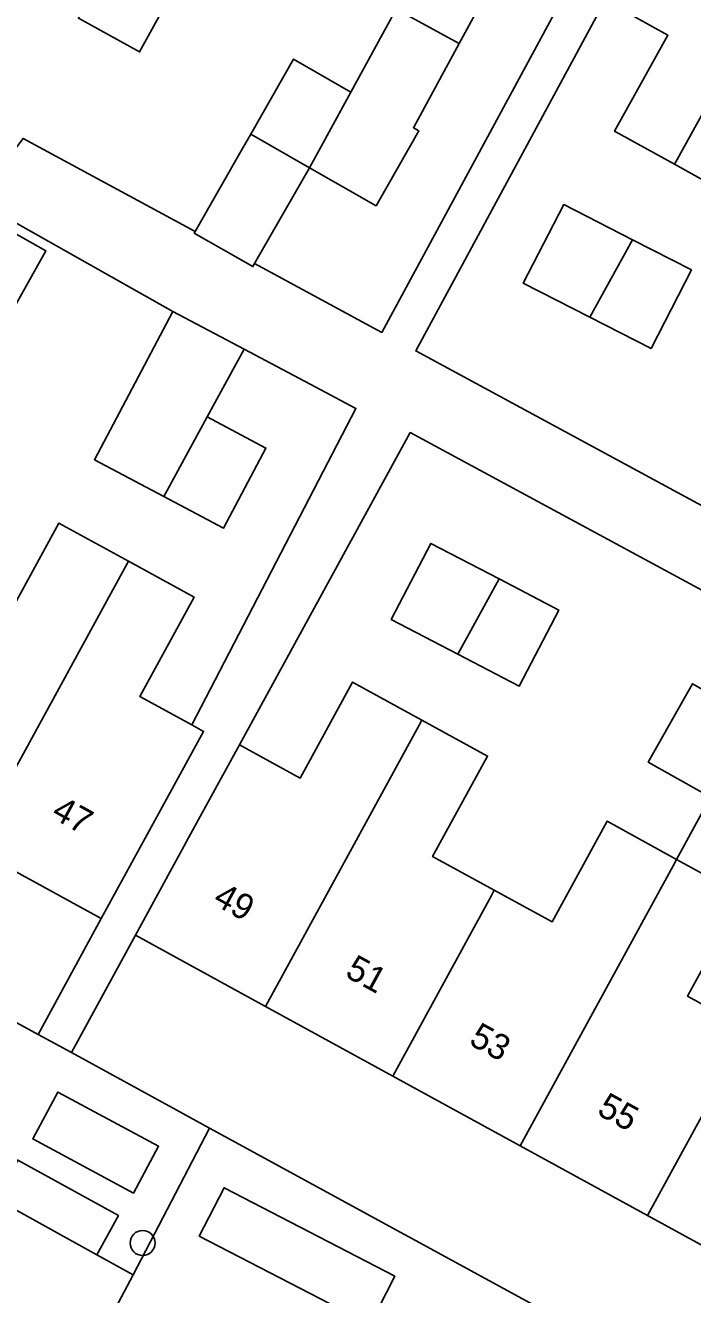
# Model space of a CAD drawing. Extents: x 158352 to 159489, y 383828 to 384603.
# Drawn here: x 158906.49 to 158932.65, y 384049.08 to 384098.81 of the extents above; entities that cross this region are included whole.
import ezdxf

# ---------------------------------------------------------------- set-up
doc = ezdxf.new("R2010")
doc.units = 0
for name, color, linetype in [('IMGEO_Boom', 7, 'Continuous'), ('IMGEO_Erf', 7, 'Continuous'), ('IMGEO_Groenvoorziening', 7, 'Continuous'), ('IMGEO_Pand', 7, 'Continuous'), ('IMGEO_Pand_nummerreeks', 7, 'Continuous'), ('IMGEO_Parkeervlak_open', 7, 'Continuous'), ('IMGEO_Rijbaan_lokaal_open', 7, 'Continuous'), ('IMGEO_Voetpad_open', 7, 'Continuous')]:
    doc.layers.add(name, color=color, linetype=linetype)

msp = doc.modelspace()

# ---------------------------------------------------------------- linework, layer by layer
at = {"layer": 'IMGEO_Boom'}
msp.add_circle((158911.089, 384051.104), 0.489, dxfattribs=at)
at = {"layer": 'IMGEO_Erf'}
for points in [[(158927.837, 384100.41), (158925.461, 384101.702), (158923.499, 384098.095), (158921.704, 384094.794), (158921.916, 384094.673), (158920.24, 384091.738), (158917.624, 384093.231), (158915.476, 384089.473), (158920.462, 384086.776)], [(158930.295, 384090.408), (158932.607, 384089.225), (158931.016, 384086.145), (158928.617, 384087.373), (158926.007, 384088.709), (158927.598, 384091.788)], [(158888.902, 384073.704), (158883.93, 384076.424), (158880.419, 384078.345), (158879.033, 384079.103), (158878.958, 384079.144), (158878.785, 384078.828), (158873.813, 384081.548), (158873.667, 384081.628), (158874.377, 384082.925), (158869.446, 384085.623), (158866.975, 384081.108), (158906.994, 384059.275), (158909.471, 384063.815), (158905.141, 384066.184), (158904.492, 384066.539), (158904.393, 384066.593), (158903.622, 384065.185), (158898.65, 384067.905), (158898.846, 384068.264), (158898.699, 384068.344), (158898.247, 384068.591), (158893.874, 384070.984)], [(158925.843, 384072.918), (158923.446, 384074.17), (158920.834, 384075.533), (158922.391, 384078.514), (158925.061, 384077.12), (158927.4, 384075.899)], [(158930.874, 384052.184), (158925.883, 384054.914), (158920.892, 384057.645), (158915.9, 384060.376), (158910.806, 384063.163), (158908.297, 384058.564), (158912.402, 384056.324), (158913.714, 384055.608), (158936.495, 384043.18), (158948.427, 384036.625), (158950.943, 384041.204), (158945.847, 384043.992), (158940.856, 384046.723), (158935.865, 384049.453)]]:
    msp.add_lwpolyline(points, close=True, dxfattribs=at)
for points in [[(158912.691, 384100.9), (158910.972, 384097.769), (158908.571, 384099.087)], [(158934.541, 384091.919), (158931.93, 384093.364), (158929.589, 384094.659), (158931.669, 384098.419), (158929.216, 384099.776), (158921.794, 384086.055), (158964.417, 384062.999)], [(158906.403, 384094.38), (158913.148, 384090.732), (158915.005, 384093.982), (158915.326, 384094.544), (158917.002, 384097.479), (158919.251, 384096.194), (158921.032, 384099.437)], [(158905.754, 384075.55), (158907.81, 384079.308), (158910.534, 384077.817), (158913.108, 384076.409), (158910.978, 384072.515), (158913.019, 384071.399), (158919.45, 384083.798), (158917.663, 384084.745), (158915.075, 384086.116), (158913.624, 384083.465), (158915.922, 384082.249), (158914.26, 384079.111), (158911.92, 384080.351), (158909.199, 384081.791), (158912.274, 384087.599), (158904.766, 384091.834)], [(158904.976, 384091.273), (158907.297, 384089.971), (158903.651, 384083.471)], [(158936.565, 384074.756), (158921.577, 384082.851), (158914.885, 384070.619), (158917.26, 384069.319), (158919.317, 384073.079), (158922.036, 384071.591), (158924.61, 384070.183), (158922.455, 384066.244), (158924.873, 384064.921), (158927.138, 384063.682), (158929.295, 384067.624), (158932.02, 384066.133), (158933.351, 384068.566), (158930.908, 384069.942), (158932.638, 384073.013), (158935.043, 384071.658)], [(158934.6, 384064.721), (158932.443, 384060.779), (158934.855, 384059.459)]]:
    msp.add_lwpolyline(points, dxfattribs=at)
at = {"layer": 'IMGEO_Groenvoorziening'}
for points in [[(158911.717, 384054.892), (158907.773, 384057.016), (158906.786, 384055.183), (158910.73, 384053.059)], [(158920.981, 384049.8), (158914.283, 384053.266), (158913.306, 384051.378), (158920.004, 384047.912)]]:
    msp.add_lwpolyline(points, close=True, dxfattribs=at)
at = {"layer": 'IMGEO_Pand'}
for points in [[(158921.032, 384099.437), (158923.499, 384098.095), (158925.461, 384101.702), (158927.837, 384100.41), (158928.924, 384102.39), (158931.33, 384106.772), (158926.75, 384109.287), (158927.171, 384110.055), (158926.933, 384110.185), (158921.119, 384099.596)], [(158937.479, 384103.394), (158932.685, 384106.046), (158930.265, 384101.672), (158929.216, 384099.776), (158931.669, 384098.419), (158929.589, 384094.659), (158931.93, 384093.364), (158932.034, 384093.551)], [(158938.691, 384094.516), (158938.817, 384094.745), (158942.168, 384100.8), (158937.479, 384103.394), (158932.034, 384093.551), (158931.93, 384093.364), (158934.541, 384091.919), (158936.613, 384095.666)], [(158910.29, 384102.218), (158908.571, 384099.087), (158910.972, 384097.769), (158912.691, 384100.9)], [(158921.916, 384094.673), (158921.704, 384094.794), (158923.499, 384098.095), (158921.032, 384099.437), (158919.251, 384096.194), (158917.624, 384093.231), (158920.24, 384091.738)], [(158919.251, 384096.194), (158917.002, 384097.479), (158915.326, 384094.544), (158917.624, 384093.231)], [(158917.624, 384093.231), (158915.326, 384094.544), (158915.005, 384093.982), (158913.148, 384090.732), (158913.113, 384090.671), (158915.411, 384089.358), (158915.476, 384089.473)], [(158928.617, 384087.373), (158930.295, 384090.408), (158927.598, 384091.788), (158926.007, 384088.709)], [(158907.297, 384089.971), (158904.976, 384091.273), (158903.082, 384087.813), (158901.398, 384084.735), (158903.651, 384083.471)], [(158928.617, 384087.373), (158931.016, 384086.145), (158932.607, 384089.225), (158930.295, 384090.408)], [(158915.075, 384086.116), (158912.274, 384087.599), (158909.199, 384081.791), (158911.92, 384080.351), (158912.062, 384080.611), (158913.624, 384083.465)], [(158915.922, 384082.249), (158913.624, 384083.465), (158912.062, 384080.611), (158911.92, 384080.351), (158914.26, 384079.111)], [(158910.534, 384077.817), (158907.81, 384079.308), (158905.754, 384075.55), (158903.506, 384076.78), (158902.922, 384075.712), (158898.846, 384068.264), (158898.65, 384067.905), (158903.622, 384065.185), (158904.393, 384066.593)], [(158923.446, 384074.17), (158925.061, 384077.12), (158922.391, 384078.514), (158920.834, 384075.533)], [(158913.482, 384071.146), (158913.019, 384071.399), (158910.978, 384072.515), (158913.108, 384076.409), (158910.534, 384077.817), (158904.393, 384066.593), (158904.492, 384066.539), (158905.141, 384066.184), (158909.471, 384063.815), (158911.871, 384068.202)], [(158923.446, 384074.17), (158925.843, 384072.918), (158927.4, 384075.899), (158925.061, 384077.12)], [(158915.9, 384060.376), (158921.929, 384071.396), (158922.036, 384071.591), (158919.317, 384073.079), (158917.26, 384069.319), (158914.885, 384070.619), (158913.206, 384067.55), (158910.806, 384063.163)], [(158933.351, 384068.566), (158935.043, 384071.658), (158932.638, 384073.013), (158930.908, 384069.942)], [(158920.892, 384057.645), (158924.763, 384064.72), (158924.873, 384064.921), (158922.455, 384066.244), (158924.61, 384070.183), (158922.036, 384071.591), (158921.929, 384071.396), (158915.9, 384060.376)], [(158937.647, 384070.192), (158935.043, 384071.658), (158933.351, 384068.566), (158932.02, 384066.133), (158934.6, 384064.721), (158935.917, 384067.121)], [(158920.892, 384057.645), (158925.883, 384054.914), (158931.879, 384065.875), (158932.02, 384066.133), (158929.295, 384067.624), (158927.138, 384063.682), (158924.873, 384064.921), (158924.763, 384064.72)], [(158930.874, 384052.184), (158934.756, 384059.278), (158934.855, 384059.459), (158932.443, 384060.779), (158934.6, 384064.721), (158932.02, 384066.133), (158931.879, 384065.875), (158925.883, 384054.914)], [(158930.874, 384052.184), (158935.865, 384049.453), (158941.937, 384060.551), (158942.026, 384060.715), (158939.374, 384062.166), (158937.193, 384058.18), (158934.855, 384059.459), (158934.756, 384059.278)]]:
    msp.add_lwpolyline(points, close=True, dxfattribs=at)
at = {"layer": 'IMGEO_Parkeervlak_open'}
msp.add_lwpolyline([(158909.296, 384050.644), (158910.141, 384052.179), (158906.198, 384054.352), (158905.352, 384052.818)], close=True, dxfattribs=at)
at = {"layer": 'IMGEO_Rijbaan_lokaal_open'}
msp.add_lwpolyline([(158909.296, 384050.644), (158905.352, 384052.818), (158904.08, 384053.52), (158900.014, 384055.761), (158898.7, 384056.486), (158894.775, 384058.649), (158893.426, 384059.393), (158889.495, 384061.56), (158888.936, 384061.868), (158884.972, 384064.054), (158882.938, 384065.175), (158881.77, 384063.085), (158880.504, 384060.82), (158890.908, 384055.136), (158894.858, 384052.979), (158896.147, 384052.274), (158900.133, 384050.097), (158902.537, 384048.783), (158906.489, 384046.625), (158908.43, 384045.564), (158909.577, 384047.711), (158910.724, 384049.857)], close=True, dxfattribs=at)
at = {"layer": 'IMGEO_Voetpad_open'}
for points in [[(158927.837, 384100.41), (158920.462, 384086.776), (158915.476, 384089.473), (158915.411, 384089.358), (158913.113, 384090.671), (158913.148, 384090.732), (158906.403, 384094.38), (158905.337, 384092.975), (158904.766, 384091.834), (158912.274, 384087.599), (158915.075, 384086.116), (158917.663, 384084.745), (158919.45, 384083.798), (158913.019, 384071.399), (158913.482, 384071.146), (158911.871, 384068.202), (158909.471, 384063.815), (158906.994, 384059.275), (158908.297, 384058.564), (158910.806, 384063.163), (158913.206, 384067.55), (158914.885, 384070.619), (158921.577, 384082.851), (158936.565, 384074.756)], [(158964.417, 384062.999), (158921.794, 384086.055), (158929.216, 384099.776)], [(158906.198, 384054.352), (158910.141, 384052.179), (158909.296, 384050.644), (158910.724, 384049.857), (158913.714, 384055.608), (158912.402, 384056.324), (158908.297, 384058.564), (158906.994, 384059.275), (158866.975, 384081.108)], [(158949.697, 384035.927), (158948.427, 384036.625), (158936.495, 384043.18), (158913.714, 384055.608), (158910.724, 384049.857), (158909.577, 384047.711), (158911.037, 384043.935), (158913.4, 384048.407), (158914.472, 384047.888)]]:
    msp.add_lwpolyline(points, dxfattribs=at)
for points in [[(158907.773, 384057.016), (158911.717, 384054.892), (158910.73, 384053.059), (158906.786, 384055.183)], [(158920.004, 384047.912), (158913.306, 384051.378), (158914.283, 384053.266), (158920.981, 384049.8)]]:
    msp.add_lwpolyline(points, close=True, dxfattribs=at)

# ---------------------------------------------------------------- texts
at = {"layer": 'IMGEO_Pand_nummerreeks'}
for s, rotation, p in [('47', 331.3177, (158907.466, 384067.784)), ('49', 331.3169, (158913.799, 384064.398)), ('51', 331.318, (158918.98, 384061.564)), ('53', 331.3169, (158923.834, 384058.908)), ('55', 331.3169, (158928.851, 384056.163))]:
    msp.add_text(s, height=1, rotation=rotation, dxfattribs=at).set_placement(p)

doc.saveas('drawing.dxf')
